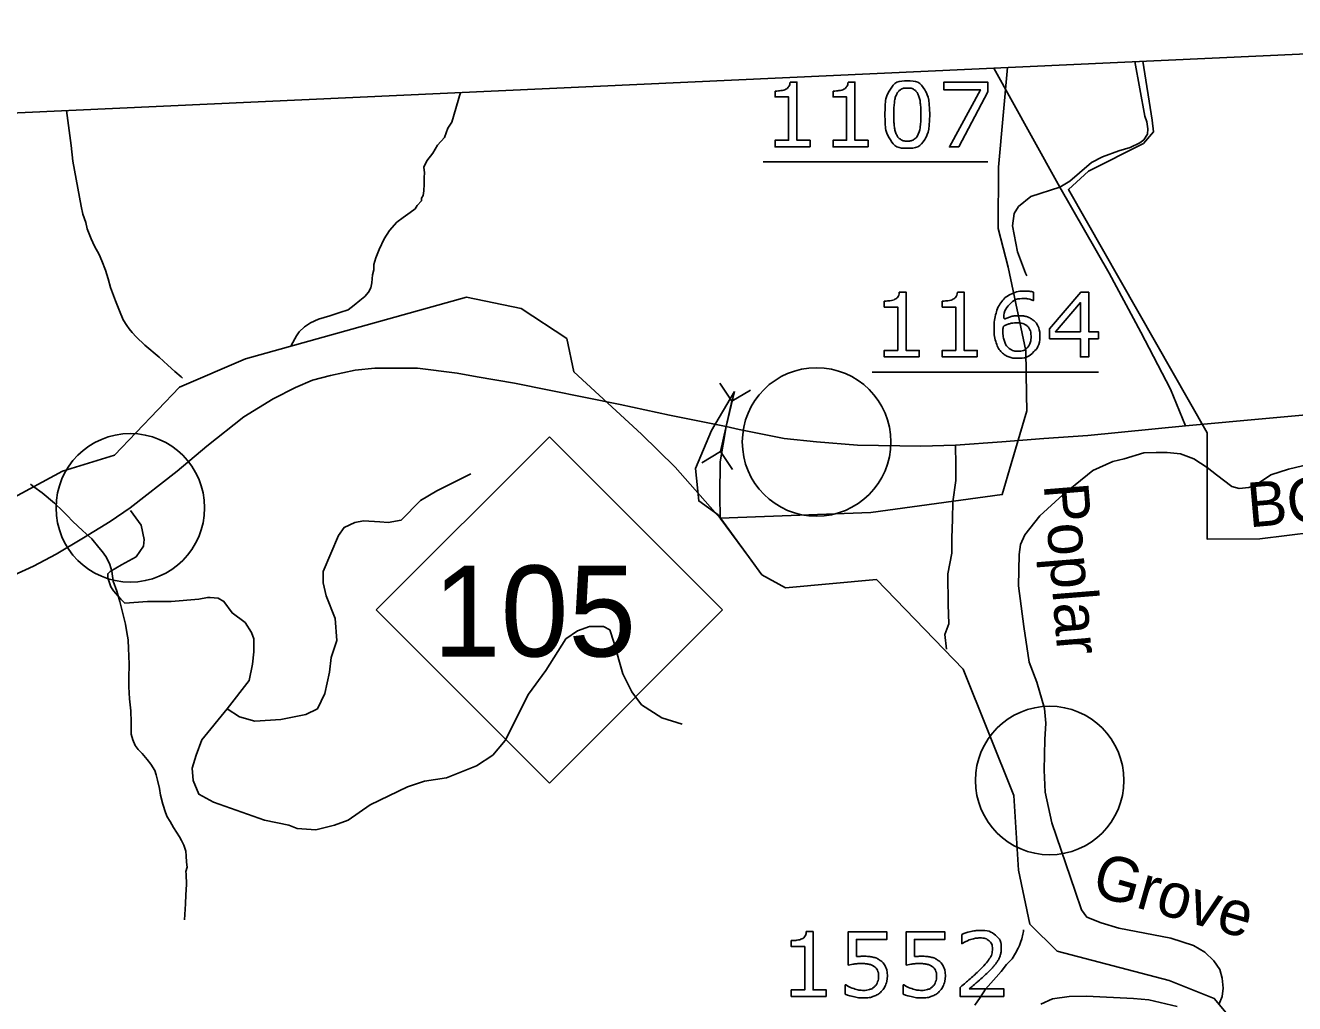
# Model space of a CAD drawing. Extents: x 1190067 to 1192950, y 891516 to 893460.
# Drawn here: x 1191031.1 to 1191116.5, y 893300.9 to 893366.8 of the extents above; entities that cross this region are included whole.
import ezdxf

# ---------------------------------------------------------------- set-up
doc = ezdxf.new("R2010")
doc.units = 0
doc.layers.add('Default', color=7, linetype='Continuous')
doc.layers.add('Prop DSN Text', color=7, linetype='Continuous')

msp = doc.modelspace()

# ---------------------------------------------------------------- linework, layer by layer
at = {"layer": 'Default'}
for p, q in [((1191080.749, 893357.59), (1191095.89, 893357.59)), ((1191088.097, 893343.45), (1191103.326, 893343.45)), ((1191077.831, 893342.691), (1191078.644, 893341.481)), ((1191079.896, 893342.228), (1191078.644, 893341.481)), ((1191077.886, 893338.094), (1191078.644, 893341.481)), ((1191054.716, 893327.442), (1191066.371, 893339.097)), ((1191066.371, 893339.097), (1191078.026, 893327.442)), ((1191076.634, 893337.347), (1191077.886, 893338.094)), ((1191078.699, 893336.885), (1191077.886, 893338.094)), ((1191066.371, 893315.787), (1191054.716, 893327.442)), ((1191078.026, 893327.442), (1191066.371, 893315.787))]:
    msp.add_line(p, q, dxfattribs=at)
for points in [[(1191100.737, 893355.891), (1191101.409, 893356.304), (1191102.049, 893356.862), (1191102.854, 893357.543), (1191103.608, 893357.936), (1191104.702, 893358.328), (1191105.466, 893358.556), (1191106.106, 893358.866), (1191106.375, 893359.072), (1191106.622, 893359.465), (1191106.655, 893359.81), (1191106.596, 893360.279), (1191106.456, 893360.666), (1191105.771, 893364.344)], [(1191106.306, 893364.369), (1191106.941, 893360.393)], [(1191096.286, 893363.91), (1191098.808, 893359.362), (1191100.737, 893355.891)], [(1191098.485, 893341.948), (1191098.43, 893344.879), (1191097.259, 893350.512), (1191096.585, 893353.108), (1191096.599, 893357.237), (1191097.214, 893363.953)], [(1191082.576, 893362.969), (1191083.029, 893362.969), (1191083.029, 893359.049), (1191083.916, 893359.049), (1191083.916, 893358.605)], [(1191086.48, 893362.969), (1191086.933, 893362.969), (1191086.933, 893359.049), (1191087.821, 893359.049), (1191087.821, 893358.605)], [(1191095.89, 893362.305), (1191093.924, 893358.605), (1191093.297, 893358.605), (1191095.386, 893362.444), (1191092.914, 893362.444), (1191092.914, 893362.955), (1191095.89, 893362.955), (1191095.89, 893362.305)], [(1191060.384, 893362.268), (1191059.792, 893360.277), (1191059.537, 893359.864), (1191059.309, 893359.24), (1191058.841, 893358.727), (1191058.511, 893358.176), (1191058.111, 893357.661), (1191057.924, 893357.246), (1191057.949, 893356.861), (1191057.94, 893356.545), (1191057.929, 893356.089), (1191057.915, 893355.635), (1191057.872, 893355.321), (1191057.763, 893355.149), (1191057.759, 893354.973), (1191057.47, 893354.666), (1191057.323, 893354.426), (1191057.002, 893354.187), (1191056.535, 893353.852), (1191056.108, 893353.547), (1191055.602, 893352.965), (1191055.236, 893352.415), (1191054.901, 893351.688), (1191054.676, 893351.134), (1191054.56, 893350.681), (1191054.549, 893350.332), (1191054.47, 893349.984), (1191054.42, 893349.46), (1191054.341, 893349.112), (1191054.196, 893348.835), (1191053.941, 893348.527), (1191053.618, 893348.256), (1191053.223, 893347.951), (1191052.832, 893347.646), (1191052.265, 893347.452), (1191051.594, 893347.224), (1191050.817, 893347), (1191050.286, 893346.768), (1191049.891, 893346.499), (1191049.533, 893346.16), (1191049.351, 893345.884), (1191048.982, 893345.229)], [(1191083.916, 893358.605), (1191081.562, 893358.605), (1191081.562, 893359.049), (1191082.468, 893359.049), (1191082.468, 893361.965), (1191081.562, 893361.965), (1191081.562, 893362.362)], [(1191087.821, 893358.605), (1191085.467, 893358.605), (1191085.467, 893359.049), (1191086.372, 893359.049), (1191086.372, 893361.965), (1191085.467, 893361.965), (1191085.467, 893362.362)], [(1191033.865, 893361.055), (1191034.183, 893358.693), (1191034.294, 893357.639), (1191034.843, 893354.613), (1191034.969, 893354.083), (1191035.163, 893353.518), (1191035.258, 893353.095), (1191035.52, 893352.422), (1191035.751, 893351.927), (1191036.051, 893351.358), (1191036.25, 893350.931), (1191036.478, 893350.296), (1191036.673, 893349.731), (1191036.833, 893349.129), (1191037.158, 893348.245), (1191037.42, 893347.572), (1191037.682, 893346.969), (1191037.915, 893346.578), (1191038.085, 893346.365), (1191038.29, 893346.113), (1191038.561, 893345.826), (1191039.14, 893345.252), (1191040.1, 893344.456), (1191040.68, 893343.914), (1191041.159, 893343.481), (1191041.572, 893343.119), (1191041.674, 893343.047)], [(1191106.941, 893360.393), (1191107.023, 893359.616), (1191106.37, 893358.84), (1191102.654, 893356.96), (1191101.306, 893355.734), (1191110.657, 893339.348)], [(1191100.737, 893355.891), (1191098.77, 893355.255), (1191097.945, 893354.589), (1191097.659, 893354.112), (1191097.532, 893353.287), (1191097.881, 893351.54), (1191098.421, 893350.111), (1191098.502, 893349.924)], [(1191100.737, 893355.891), (1191104.053, 893350.111), (1191106.18, 893346.141), (1191108.179, 893342.299), (1191109.194, 893339.822)], [(1191089.924, 893348.829), (1191090.377, 893348.829), (1191090.377, 893344.909), (1191091.265, 893344.909), (1191091.265, 893344.465)], [(1191093.829, 893348.829), (1191094.281, 893348.829), (1191094.281, 893344.909), (1191095.169, 893344.909), (1191095.169, 893344.465)], [(1191098.964, 893348.829), (1191098.964, 893348.268), (1191098.935, 893348.268)], [(1191103.326, 893345.69), (1191102.68, 893345.69), (1191102.68, 893344.465), (1191102.119, 893344.465), (1191102.119, 893345.69), (1191100.035, 893345.69), (1191100.035, 893346.362), (1191102.142, 893348.815), (1191102.68, 893348.815), (1191102.68, 893346.159), (1191103.326, 893346.159), (1191103.326, 893345.69)], [(1190953.417, 893329.319), (1190953.914, 893329.356), (1190959.137, 893331.201), (1190974.729, 893335.429), (1190977.391, 893336.524), (1190986.682, 893335.133), (1190992.126, 893331.346), (1190997.164, 893328.719), (1191000.962, 893329.045), (1191004.497, 893330.123), (1191008.574, 893329.869), (1191025.304, 893333.385), (1191030.029, 893334.842), (1191033.582, 893336.78), (1191037.099, 893337.859), (1191041.458, 893342.425), (1191045.902, 893344.347), (1191060.786, 893348.481), (1191064.46, 893347.731), (1191067.535, 893345.705), (1191068.023, 893343.455)], [(1191091.265, 893344.465), (1191088.91, 893344.465), (1191088.91, 893344.909), (1191089.816, 893344.909), (1191089.816, 893347.824), (1191088.91, 893347.824), (1191088.91, 893348.222)], [(1191095.169, 893344.465), (1191092.815, 893344.465), (1191092.815, 893344.909), (1191093.72, 893344.909), (1191093.72, 893347.824), (1191092.815, 893347.824), (1191092.815, 893348.222)], [(1191102.119, 893346.159), (1191102.119, 893348.123), (1191100.431, 893346.159), (1191102.119, 893346.159)], [(1191029.529, 893329.408), (1191031.632, 893330.388), (1191033.168, 893331.19), (1191035.016, 893332.281), (1191036.796, 893333.395), (1191038.154, 893334.308), (1191041.304, 893336.781), (1191043.307, 893338.451), (1191045.8, 893340.434), (1191047.781, 893341.636), (1191049.284, 893342.416), (1191050.419, 893342.906), (1191051.643, 893343.218), (1191053.29, 893343.574), (1191054.626, 893343.708), (1191057.497, 893343.708), (1191060.157, 893343.374), (1191061.515, 893343.129), (1191064.008, 893342.706), (1191071.142, 893341.258), (1191074.459, 893340.545), (1191078.265, 893339.788), (1191079.133, 893339.587), (1191082.171, 893338.986), (1191084.353, 893338.741), (1191087.113, 893338.518), (1191091.364, 893338.451), (1191093.697, 893338.532), (1191096.829, 893338.741), (1191099.656, 893338.986)], [(1191068.023, 893343.455), (1191072.576, 893339.274)], [(1191115.518, 893296.022), (1191111.126, 893301.279), (1191108.098, 893302.489), (1191100.556, 893304.478), (1191098.718, 893306.295), (1191097.946, 893309.931), (1191097.633, 893314.936), (1191094.219, 893323.448), (1191088.393, 893329.482), (1191082.251, 893328.915), (1191080.674, 893329.808), (1191077.718, 893333.831), (1191076.422, 893334.776), (1191076.196, 893336.963), (1191077.279, 893339.525), (1191078.821, 893342.14)], [(1191079.834, 893330.946), (1191077.862, 893333.617), (1191077.834, 893335.143), (1191077.854, 893337.403), (1191078.265, 893339.788), (1191078.821, 893342.14)], [(1191097.46, 893337.261), (1191098.505, 893340.827), (1191098.485, 893341.948)], [(1191109.194, 893339.822), (1191120.497, 893340.855)], [(1191120.497, 893340.855), (1191120.573, 893340.132), (1191120.413, 893339.686), (1191119.554, 893338.699), (1191118.345, 893337.648), (1191117.74, 893337.298), (1191117.072, 893337.138), (1191116.117, 893336.916), (1191114.94, 893336.533), (1191113.89, 893335.833), (1191113.444, 893335.674), (1191112.808, 893335.61), (1191112.299, 893335.737), (1191111.28, 893336.533), (1191110.657, 893337.027)], [(1191099.656, 893338.986), (1191102.604, 893339.183), (1191109.194, 893339.822)], [(1191072.576, 893339.274), (1191074.837, 893337.042), (1191077.862, 893333.617)], [(1191110.657, 893339.348), (1191110.657, 893332.196), (1191114.194, 893332.231), (1191117.823, 893332.68), (1191122.275, 893333.265), (1191124.459, 893333.504), (1191129.27, 893333.466), (1191131.311, 893332.609), (1191139.12, 893328.9), (1191146.35, 893325.622), (1191148.072, 893325.034), (1191151.86, 893323.614), (1191153.289, 893322.511), (1191154.596, 893319.896), (1191154.147, 893318.302), (1191154.162, 893317.632), (1191153.987, 893316.78), (1191154.637, 893315.564), (1191156.352, 893313.113), (1191155.821, 893316.218)], [(1191093.697, 893338.532), (1191093.726, 893337.17), (1191093.726, 893336.159), (1191093.532, 893334.72), (1191093.493, 893333.553), (1191093.454, 893332.269), (1191093.454, 893331.258), (1191093.182, 893329.857), (1191093.221, 893327.796), (1191093.26, 893326.512), (1191092.987, 893325.773), (1191093.104, 893324.801)], [(1191110.657, 893337.027), (1191109.744, 893337.616), (1191108.847, 893337.936), (1191107.949, 893338.032), (1191107.212, 893338.032), (1191106.379, 893338), (1191105.065, 893337.616), (1191104.296, 893337.423), (1191102.95, 893336.814), (1191100.931, 893335.178), (1191099.393, 893333.767), (1191098.368, 893332.485), (1191098.079, 893331.843), (1191097.983, 893331.17), (1191097.951, 893329.053), (1191098.304, 893326.328), (1191098.672, 893323.922), (1191099.185, 893322.576), (1191099.698, 893320.812), (1191099.794, 893319.818), (1191099.73, 893318.727), (1191099.665, 893316.643), (1191099.746, 893315.168), (1191100.194, 893313.115), (1191101.764, 893308.498), (1191102.197, 893307.247), (1191102.55, 893306.766), (1191103.511, 893306.381), (1191104.697, 893306.028), (1191108.19, 893305.355), (1191109.728, 893304.842), (1191110.497, 893304.393), (1191111.106, 893303.816), (1191111.49, 893303.238), (1191111.651, 893302.661), (1191111.715, 893301.988), (1191111.651, 893301.411), (1191111.458, 893300.93)], [(1191077.862, 893333.617), (1191088.007, 893333.998), (1191096.856, 893335.199), (1191097.46, 893337.261)], [(1191044.676, 893320.782), (1191045.496, 893320.235), (1191046.535, 893319.961), (1191048.286, 893320.071), (1191049.981, 893320.399), (1191050.747, 893320.782), (1191051.24, 893321.822), (1191051.568, 893323.245), (1191051.677, 893324.231), (1191052.06, 893325.38), (1191051.951, 893326.858), (1191051.349, 893328.391), (1191051.13, 893329.267), (1191051.13, 893330.033), (1191052.169, 893332.441), (1191052.552, 893332.989), (1191053.263, 893333.317), (1191053.865, 893333.427), (1191054.959, 893333.372), (1191055.506, 893333.317), (1191056.381, 893333.481), (1191057.694, 893334.795), (1191058.788, 893335.452), (1191061.086, 893336.601)], [(1191041.808, 893306.582), (1191041.873, 893307.665), (1191041.889, 893308.261), (1191041.943, 893308.961), (1191041.925, 893309.661), (1191041.898, 893309.836), (1191041.974, 893310.116), (1191041.948, 893310.466), (1191041.925, 893310.888), (1191041.898, 893311.204), (1191041.769, 893311.593), (1191041.602, 893311.912), (1191041.469, 893312.16), (1191041.066, 893312.802), (1191040.832, 893313.193), (1191040.631, 893313.515), (1191040.533, 893313.798), (1191040.337, 893314.363), (1191040.178, 893314.962), (1191040.12, 893315.42), (1191039.996, 893315.983), (1191039.899, 893316.337), (1191039.804, 893316.62), (1191039.535, 893317.045), (1191039.298, 893317.368), (1191038.959, 893317.763), (1191038.687, 893318.05), (1191038.482, 893318.301), (1191038.319, 893318.691), (1191038.224, 893319.077), (1191038.211, 893319.882), (1191038.197, 893320.654), (1191038.112, 893321.461), (1191038.064, 893322.268), (1191038.048, 893322.9), (1191038.069, 893323.74), (1191038.051, 893324.369), (1191038.03, 893324.827), (1191038.01, 893325.423), (1191037.919, 893325.914), (1191037.829, 893326.478), (1191037.45, 893327.994), (1191037.257, 893328.699), (1191036.995, 893329.372), (1191036.91, 893330.041), (1191036.781, 893330.498), (1191036.648, 893330.784), (1191036.516, 893331.031), (1191036.279, 893331.352), (1191036.042, 893331.641), (1191035.566, 893332.214), (1191034.951, 893332.756), (1191034.269, 893333.405), (1191033.93, 893333.764), (1191033.623, 893334.087), (1191033.042, 893334.629), (1191032.218, 893335.316), (1191031.669, 893335.716), (1191031.429, 893335.897)], [(1191038.166, 893334.138), (1191038.877, 893333.153), (1191039.096, 893332.168), (1191039.041, 893331.73), (1191038.549, 893331.018), (1191037.565, 893330.471), (1191036.799, 893330.033), (1191036.635, 893329.869), (1191036.635, 893329.595), (1191036.853, 893328.993), (1191037.018, 893328.719), (1191037.51, 893328.172), (1191037.783, 893327.898), (1191039.315, 893328.008), (1191040.901, 893328.008), (1191042.761, 893328.172), (1191043.363, 893328.281), (1191043.527, 893328.281), (1191044.074, 893328.227), (1191044.457, 893328.008), (1191045.004, 893327.241), (1191045.879, 893326.584), (1191046.317, 893325.928), (1191046.481, 893325.49), (1191046.481, 893324.614), (1191046.371, 893323.793), (1191046.152, 893322.698), (1191044.676, 893320.782), (1191042.98, 893318.702), (1191042.597, 893317.662), (1191042.323, 893316.786), (1191042.378, 893315.965), (1191042.761, 893315.035), (1191043.746, 893314.487), (1191047.192, 893313.283), (1191048.833, 893312.955), (1191049.38, 893312.736), (1191050.638, 893312.626), (1191051.896, 893312.955), (1191052.826, 893313.283), (1191054.303, 893314.323), (1191056.819, 893315.527), (1191057.968, 893315.911), (1191059.445, 893316.129), (1191061.468, 893316.951), (1191062.562, 893317.662), (1191063.383, 893318.647), (1191064.969, 893321.767), (1191066.118, 893323.355), (1191067.485, 893325.49), (1191068.251, 893326.037), (1191069.072, 893326.311), (1191069.783, 893326.311), (1191070.002, 893326.311), (1191070.439, 893326.092), (1191070.713, 893325.271), (1191071.314, 893323.136), (1191071.916, 893321.932), (1191072.573, 893321.056), (1191073.94, 893320.18), (1191075.308, 893319.742)], [(1191115.518, 893296.022), (1191111.126, 893301.279), (1191108.098, 893302.489), (1191100.556, 893304.478), (1191098.718, 893306.295), (1191097.946, 893309.931), (1191097.633, 893314.936), (1191094.219, 893323.448), (1191088.393, 893329.482), (1191082.251, 893328.915), (1191080.674, 893329.808), (1191079.834, 893330.946)], [(1191083.661, 893305.783), (1191084.114, 893305.783), (1191084.114, 893301.863), (1191085.002, 893301.863), (1191085.002, 893301.419)], [(1191086.474, 893303.528), (1191086.474, 893305.769), (1191089.091, 893305.769), (1191089.091, 893305.257), (1191087.035, 893305.257), (1191087.035, 893304.101)], [(1191090.379, 893303.528), (1191090.379, 893305.769), (1191092.996, 893305.769), (1191092.996, 893305.257), (1191090.94, 893305.257), (1191090.94, 893304.101)], [(1191094.153, 893304.977), (1191094.124, 893304.977), (1191094.124, 893305.59)], [(1191094.996, 893300.835), (1191095.358, 893301.352), (1191095.724, 893301.901), (1191096.087, 893302.311), (1191096.447, 893302.722), (1191096.772, 893303.099), (1191097.136, 893303.578), (1191097.531, 893303.953), (1191097.752, 893304.334), (1191097.935, 893304.678), (1191098.012, 893304.852), (1191098.086, 893305.06), (1191098.163, 893305.302), (1191098.242, 893305.615), (1191098.281, 893305.79), (1191098.285, 893305.895)], [(1191085.002, 893301.419), (1191082.648, 893301.419), (1191082.648, 893301.863), (1191083.553, 893301.863), (1191083.553, 893304.778), (1191082.648, 893304.778), (1191082.648, 893305.176)], [(1191086.286, 893301.58), (1191086.286, 893302.196), (1191086.327, 893302.196)], [(1191090.191, 893301.58), (1191090.191, 893302.196), (1191090.232, 893302.196)], [(1191096.965, 893301.419), (1191094.017, 893301.419), (1191094.017, 893302.034)], [(1191094.622, 893301.923), (1191096.965, 893301.923), (1191096.965, 893301.419)], [(1191108.638, 893300.737), (1191106.716, 893301.186), (1191105.69, 893301.282), (1191102.518, 893301.443), (1191101.364, 893301.411), (1191100.242, 893301.25), (1191099.441, 893300.898)]]:
    msp.add_lwpolyline(points, dxfattribs=at)
for points in [[(1191081.562, 893362.362), (1191081.746, 893362.362), (1191081.956, 893362.393), (1191082.167, 893362.424), (1191082.275, 893362.482), (1191082.409, 893362.555), (1191082.487, 893362.667), (1191082.564, 893362.78), (1191082.576, 893362.969)], [(1191085.467, 893362.362), (1191085.651, 893362.362), (1191085.861, 893362.393), (1191086.071, 893362.424), (1191086.18, 893362.482), (1191086.314, 893362.555), (1191086.391, 893362.667), (1191086.469, 893362.78), (1191086.48, 893362.969)], [(1191091.967, 893360.783), (1191091.967, 893359.61), (1191091.601, 893359.061), (1191091.234, 893358.513), (1191090.463, 893358.513), (1191089.681, 893358.513), (1191089.32, 893359.069), (1191088.959, 893359.625), (1191088.959, 893360.777), (1191088.959, 893361.939), (1191089.324, 893362.493), (1191089.69, 893363.048), (1191090.463, 893363.048), (1191091.246, 893363.048), (1191091.607, 893362.484), (1191091.967, 893361.921), (1191091.967, 893360.783)], [(1191091.199, 893359.455), (1191091.301, 893359.692), (1191091.338, 893360.012), (1191091.374, 893360.333), (1191091.374, 893360.783), (1191091.374, 893361.228), (1191091.338, 893361.555), (1191091.301, 893361.883), (1191091.196, 893362.111), (1191091.094, 893362.337), (1191090.917, 893362.451), (1191090.741, 893362.565), (1191090.463, 893362.565), (1191090.189, 893362.565), (1191090.009, 893362.451), (1191089.83, 893362.337), (1191089.725, 893362.105), (1191089.625, 893361.889), (1191089.589, 893361.541), (1191089.553, 893361.193), (1191089.553, 893360.777), (1191089.553, 893360.321), (1191089.585, 893360.014), (1191089.617, 893359.707), (1191089.722, 893359.464), (1191089.818, 893359.236), (1191089.995, 893359.116), (1191090.171, 893358.996), (1191090.463, 893358.996), (1191090.738, 893358.996), (1191090.919, 893359.11), (1191091.1, 893359.224), (1191091.199, 893359.455)], [(1191088.91, 893348.222), (1191089.094, 893348.222), (1191089.305, 893348.253), (1191089.515, 893348.283), (1191089.623, 893348.342), (1191089.757, 893348.415), (1191089.835, 893348.527), (1191089.912, 893348.64), (1191089.924, 893348.829)], [(1191092.815, 893348.222), (1191092.999, 893348.222), (1191093.209, 893348.253), (1191093.42, 893348.283), (1191093.528, 893348.342), (1191093.662, 893348.415), (1191093.739, 893348.527), (1191093.817, 893348.64), (1191093.829, 893348.829)], [(1191099.386, 893345.875), (1191099.386, 893345.211), (1191098.95, 893344.792), (1191098.513, 893344.373), (1191097.879, 893344.373), (1191097.558, 893344.373), (1191097.295, 893344.472), (1191097.032, 893344.572), (1191096.83, 893344.767), (1191096.579, 893345.01), (1191096.443, 893345.41), (1191096.308, 893345.811), (1191096.308, 893346.375), (1191096.308, 893346.953), (1191096.432, 893347.4), (1191096.556, 893347.848), (1191096.828, 893348.195), (1191097.085, 893348.526), (1191097.491, 893348.711), (1191097.897, 893348.897), (1191098.438, 893348.897), (1191098.61, 893348.897), (1191098.727, 893348.882), (1191098.844, 893348.867), (1191098.964, 893348.829)], [(1191098.935, 893348.268), (1191098.853, 893348.313), (1191098.688, 893348.353), (1191098.523, 893348.393), (1191098.351, 893348.393), (1191097.724, 893348.393), (1191097.35, 893348), (1191096.976, 893347.607), (1191096.915, 893346.938), (1191097.16, 893347.087), (1191097.398, 893347.165), (1191097.636, 893347.242), (1191097.948, 893347.242), (1191098.225, 893347.242), (1191098.437, 893347.191), (1191098.648, 893347.14), (1191098.87, 893346.985), (1191099.127, 893346.807), (1191099.256, 893346.535), (1191099.386, 893346.263), (1191099.386, 893345.875)], [(1191098.793, 893345.849), (1191098.793, 893346.12), (1191098.713, 893346.298), (1191098.633, 893346.476), (1191098.449, 893346.607), (1191098.315, 893346.701), (1191098.152, 893346.73), (1191097.988, 893346.759), (1191097.811, 893346.759), (1191097.563, 893346.759), (1191097.35, 893346.701), (1191097.137, 893346.642), (1191096.912, 893346.52), (1191096.906, 893346.456), (1191096.904, 893346.396), (1191096.901, 893346.336), (1191096.901, 893346.246), (1191096.901, 893345.785), (1191096.995, 893345.518), (1191097.09, 893345.251), (1191097.256, 893345.097), (1191097.391, 893344.968), (1191097.547, 893344.908), (1191097.703, 893344.849), (1191097.886, 893344.849), (1191098.309, 893344.849), (1191098.551, 893345.107), (1191098.793, 893345.365), (1191098.793, 893345.849)], [(1191082.648, 893305.176), (1191082.832, 893305.176), (1191083.042, 893305.206), (1191083.252, 893305.237), (1191083.361, 893305.295), (1191083.495, 893305.368), (1191083.572, 893305.481), (1191083.65, 893305.593), (1191083.661, 893305.783)], [(1191094.017, 893302.034), (1191094.325, 893302.297), (1191094.634, 893302.559), (1191094.943, 893302.822), (1191095.209, 893303.082), (1191095.771, 893303.625), (1191095.979, 893303.945), (1191096.187, 893304.265), (1191096.187, 893304.636), (1191096.187, 893304.974), (1191095.963, 893305.165), (1191095.739, 893305.357), (1191095.337, 893305.357), (1191095.07, 893305.357), (1191094.76, 893305.263), (1191094.449, 893305.17), (1191094.153, 893304.977)], [(1191094.124, 893305.59), (1191094.332, 893305.692), (1191094.678, 893305.776), (1191095.025, 893305.861), (1191095.35, 893305.861), (1191096.019, 893305.861), (1191096.4, 893305.538), (1191096.78, 893305.216), (1191096.78, 893304.664), (1191096.78, 893304.416), (1191096.717, 893304.201), (1191096.654, 893303.987), (1191096.531, 893303.794), (1191096.417, 893303.613), (1191096.264, 893303.438), (1191096.111, 893303.263), (1191095.891, 893303.05), (1191095.578, 893302.743), (1191095.245, 893302.456), (1191094.912, 893302.168), (1191094.622, 893301.923)], [(1191086.327, 893302.196), (1191086.567, 893302.044), (1191086.888, 893301.937), (1191087.209, 893301.831), (1191087.519, 893301.831), (1191087.726, 893301.831), (1191087.921, 893301.889), (1191088.115, 893301.948), (1191088.267, 893302.094), (1191088.395, 893302.22), (1191088.461, 893302.396), (1191088.527, 893302.571), (1191088.527, 893302.803), (1191088.527, 893303.028), (1191088.449, 893303.183), (1191088.372, 893303.339), (1191088.235, 893303.432), (1191088.083, 893303.544), (1191087.866, 893303.589), (1191087.648, 893303.634), (1191087.379, 893303.634), (1191087.123, 893303.634), (1191086.885, 893303.599), (1191086.647, 893303.563), (1191086.474, 893303.528)], [(1191087.035, 893304.101), (1191087.161, 893304.113), (1191087.293, 893304.119), (1191087.424, 893304.125), (1191087.521, 893304.125), (1191087.874, 893304.125), (1191088.14, 893304.065), (1191088.407, 893304.005), (1191088.629, 893303.853), (1191088.863, 893303.692), (1191088.991, 893303.437), (1191089.12, 893303.183), (1191089.12, 893302.8)], [(1191090.232, 893302.196), (1191090.471, 893302.044), (1191090.793, 893301.937), (1191091.114, 893301.831), (1191091.424, 893301.831), (1191091.631, 893301.831), (1191091.825, 893301.889), (1191092.02, 893301.948), (1191092.171, 893302.094), (1191092.3, 893302.22), (1191092.366, 893302.396), (1191092.431, 893302.571), (1191092.431, 893302.803), (1191092.431, 893303.028), (1191092.354, 893303.183), (1191092.277, 893303.339), (1191092.14, 893303.432), (1191091.988, 893303.544), (1191091.77, 893303.589), (1191091.553, 893303.634), (1191091.284, 893303.634), (1191091.027, 893303.634), (1191090.789, 893303.599), (1191090.551, 893303.563), (1191090.379, 893303.528)], [(1191090.94, 893304.101), (1191091.066, 893304.113), (1191091.197, 893304.119), (1191091.329, 893304.125), (1191091.425, 893304.125), (1191091.779, 893304.125), (1191092.045, 893304.065), (1191092.311, 893304.005), (1191092.533, 893303.853), (1191092.767, 893303.692), (1191092.896, 893303.437), (1191093.024, 893303.183), (1191093.024, 893302.8)], [(1191089.12, 893302.8), (1191089.12, 893302.496), (1191089.009, 893302.218), (1191088.898, 893301.94), (1191088.705, 893301.75), (1191088.495, 893301.546), (1191088.204, 893301.436), (1191087.913, 893301.326), (1191087.531, 893301.326), (1191087.174, 893301.326), (1191086.844, 893301.401), (1191086.514, 893301.475), (1191086.286, 893301.58)], [(1191093.024, 893302.8), (1191093.024, 893302.496), (1191092.913, 893302.218), (1191092.802, 893301.94), (1191092.61, 893301.75), (1191092.399, 893301.546), (1191092.109, 893301.436), (1191091.818, 893301.326), (1191091.435, 893301.326), (1191091.079, 893301.326), (1191090.749, 893301.401), (1191090.419, 893301.475), (1191090.191, 893301.58)]]:
    msp.add_open_spline(points, degree=3, dxfattribs=at)
at = {"layer": 'Prop DSN Text'}
msp.add_lwpolyline([(1191159.03, 893366.781), (1190838.384, 893352.111), (1190851.291, 893069.992), (1191171.937, 893084.661)], dxfattribs=at)
msp.add_lwpolyline([(1191159.03, 893366.781), (1190838.384, 893352.111), (1190851.291, 893069.992), (1191171.937, 893084.661)], dxfattribs=at)
msp.add_lwpolyline([(1191159.03, 893366.781), (1190838.384, 893352.111), (1190851.291, 893069.992), (1191171.937, 893084.661)], dxfattribs=at)
for centre in [(1191084.353, 893338.741), (1191084.353, 893338.741), (1191038.154, 893334.308), (1191038.154, 893334.308), (1191100.044, 893315.958)]:
    msp.add_circle(centre, 5, dxfattribs=at)

# ---------------------------------------------------------------- texts
at = {"layer": 'Default'}
for s, rotation, p in [('BOONE ', 4.96323, (1191113.471, 893332.989)), ('Poplar', 274.63398, (1191099.641, 893335.881)), ('Grove', 344.09554, (1191102.764, 893308.292))]:
    msp.add_text(s, height=3, rotation=rotation, dxfattribs=at).set_placement(p)
msp.add_text('105', height=6.125, dxfattribs=at).set_placement((1191058.535, 893324.302))

doc.saveas('drawing.dxf')
